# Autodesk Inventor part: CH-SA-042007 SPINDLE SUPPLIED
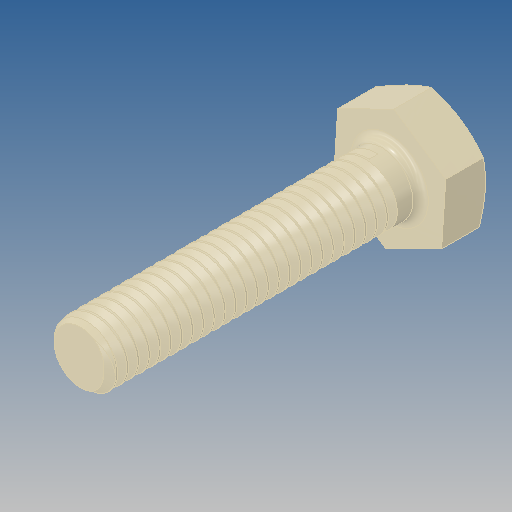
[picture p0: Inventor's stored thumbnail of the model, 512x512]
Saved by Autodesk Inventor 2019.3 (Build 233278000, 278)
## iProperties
Created: 2012-09
Part Number: CH-SA-042007 SPINDLE SUPPLIED
Material: Ogólny
Document SubType Name: Modeling
Designer: CADENGINEERING4
Density: 1 g/cm^3
Appearance: Jasnobeżowa
Mass: 0.332541 g
Surface Area: 5.38894 cm^2
Volume: 0.332541 cm^3
Author: CADENGINEERING4
Revision Number: ÈÎºÎ
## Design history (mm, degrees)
feature "ÇÐ³ý-É¨Ãè1"
node "Bryła1"
